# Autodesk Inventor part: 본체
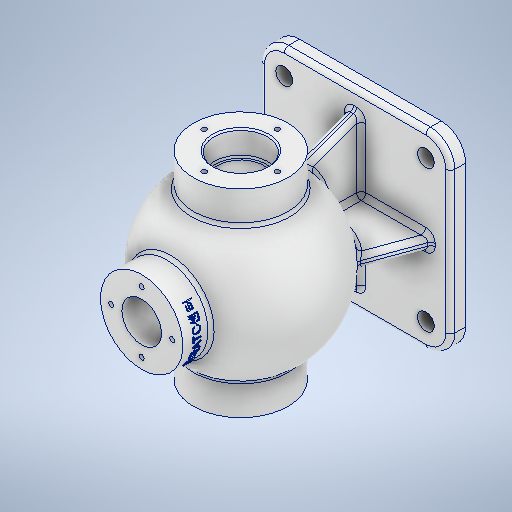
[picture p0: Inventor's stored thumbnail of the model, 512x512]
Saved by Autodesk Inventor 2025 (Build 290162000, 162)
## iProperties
Created: 2025-08
Part Number: 본체
Material: 알루미늄 6061
Document SubType Name: Modeling
Designer: infra028
Density: 2.7 g/cm^3
Appearance: 알루미늄 - 평지
Mass: 1526.56 g
Surface Area: 1173.66 cm^2
Volume: 565.392 cm^3
Author: infra028
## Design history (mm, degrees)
sketch "스케치1"
  geometry: L1 (-62.5, 62.5)-(62.5, 62.5); L2 (62.5, 62.5)-(62.5, -62.5); L3 (62.5, -62.5)-(-62.5, -62.5); L4 (-62.5, -62.5)-(-62.5, 62.5); L5 (-62.5, 62.5)-(62.5, -62.5); L6 (62.5, 62.5)-(-62.5, -62.5); 1 further point
  constraints: 12 end point, 2 midpoint, 2 parallel, 1 horizontal, 1 perpendicular
  dimensions: "d0" = 125 distance of L2.end L3.end; "d1" = 125 distance of L1.end L2.end
extrude "돌출1" new body sketch "스케치1" distance "d2" = 10; taper "d3" = 0 deg
sketch "스케치2"
  geometry: L1 (-46.5, 46.5)-(46.5, 46.5); L2 (46.5, 46.5)-(46.5, -46.5); L3 (46.5, -46.5)-(-46.5, -46.5); L4 (-46.5, -46.5)-(-46.5, 46.5); L5 (62.5, -62.5)-(62.5, 62.5) reference; L6 (-62.5, 62.5)-(-62.5, -62.5) reference; L7 (62.5, 62.5)-(-62.5, 62.5) reference; L8 (-62.5, -62.5)-(62.5, -62.5) reference; 5 further points
  constraints: 8 end point, 4 coincident, 2 parallel, 1 horizontal, 1 perpendicular
  dimensions: "d4" = 93 distance of L2.end L3.end; "d5" = 93 distance of L1.end L2.end; "d6" = 16 distance between parallel lines of L5 L2 (= d7); "d7" = 16 distance between parallel lines of L4 L6 (derived); "d8" = 16 distance between parallel lines of L1 L7 (= d9); "d9" = 16 distance between parallel lines of L8 L3 (derived)
hole "구멍1" sketch "스케치2" at (46.5, 46.5), (-46.5, -46.5), (46.5, -46.5), (-46.5, 46.5) diameter "d10" = 11; stored, may be unused: countersink angle "d14" = 90 deg, drill point angle "d16" = 0 deg; dims "d11" = 8, "d12" = 4, "d13" = 2, "d15" = 11.8
sketch "스케치4"
  geometry: L1 (54, 85)-(-54, 85); L2 (62.5, 0)-(-62.5, 0) reference; L3 (62.5, 0)-(62.5, 10) reference; A1 r 54 centre (0, 85) between (54, 85) and (-54, 85); 3 further points
  constraints: 2 end point, 2 midpoint, 2 point on circle, 1 centre point, 1 horizontal
  dimensions: "d18" = 108 diameter of A1; "d20" = 85 distance from line of L2 point (0, 85); "d21" = 62.5 horizontal distance of A1.centre point (62.5, 5); "d22" = 8.5 distance from line of L1.start L3
revolve "회전1" sketch "스케치4" stored, may be unused: angle "d19" = 360 deg
sketch "스케치5"
  geometry: L1 (-62.5, 10)-(62.5, 10) reference; L2 (-34.447, 54.104)-(-50.5, 10); L3 (43.084, 10)-(-50.5, 10); L4 (62.5, 0)-(62.5, 10) reference; L5 (-62.5, 0)-(-62.5, 10) reference; L6 (50.5, 10)-(34.447, 54.104); L7 (34.447, 54.104)-(-34.447, 54.104); 1 further point
  constraints: 8 end point, 3 point on line, 1 horizontal
  dimensions: "d24" = 20 deg angle of L2 L5; "d25" = 20 deg angle of L4 L6; "d26" = 12 distance from line of L6.start L4; "d27" = 12 distance of L1.start L2.end; "d28" = 44.10432 distance between parallel lines of L1 L7
extrude "돌출2" join sketch "스케치5" stored distance "d29" = 8; taper "d30" = 0 deg
sketch "스케치6"
  geometry: L1 (50.5, 10)-(33.738, 56.054); L2 (62.5, 0)-(62.5, 10) reference; L3 (-62.5, 10)-(62.5, 10) reference; L4 (-50.5, 10)-(-33.738, 56.054); L5 (-62.5, 0)-(-62.5, 10) reference; L6 (33.738, 56.054)-(-33.738, 56.054); 1 further point
  constraints: 6 end point, 2 point on line, 1 horizontal
  dimensions: "d31" = 20 deg angle of L2 L1; "d32" = 12 distance of L2.end L1.start; "d33" = 20 deg angle of L5 L4; "d34" = 12 distance of L3.start L4.start; "d35" = 46.0543 distance between parallel lines of L3 L6
extrude "돌출3" join sketch "스케치6" stored distance "d36" = 8; taper "d37" = 0 deg
sketch "스케치7"
  geometry: L1 (0, 85)-(-65, 85); L2 (-65, 85)-(-65, 116); L3 (-65, 116)-(-37.385, 116); L4 (-37.385, 116)-(-37.385, 85); 1 further point
  constraints: 8 end point, 2 horizontal, 2 perpendicular, 1 point on line
  dimensions: "d38" = 65 distance of L1.start L1.end; "d39" = 31 distance of L1.end L2.end; "d40" = 27.61518 distance between parallel lines of L4 L2; "d41" = 85 distance from line of point (0, 0) L1; "d42" = 37.38482 distance from line of point (0, 0) L4
revolve "회전2" sketch "스케치7" stored, may be unused: angle "d43" = 360 deg
sketch "스케치8"
  geometry: L1 (0, 85)-(0, 150); L2 (27, 150)-(-27, 150); L3 (27, 150)-(27, 124.409); L4 (27, 124.409)-(-27, 124.409); L5 (-27, 124.409)-(-27, 150); L6 (27, 137.204)-(-27, 137.204); A1 r 54 centre (0, 85) between (37.385, 46.034) and (-37.385, 46.034) reference; 5 further points
  constraints: 12 end point, 3 midpoint, 2 perpendicular, 2 vertical, 1 coincident, 1 horizontal
  dimensions: "d44" = 65 distance of L1.end L1.start; "d45" = 54 distance of L2.start L2.end; "d46" = 25.59142 distance between parallel lines of L4 L2
revolve "회전3" sketch "스케치8" stored, may be unused: angle "d47" = 360 deg
sketch "스케치9"
  geometry: L1 (65, 116)-(65, 54) reference; L2 (-65, 116)-(-65, 54) reference; L3 (65, 85)-(-65, 85); L4 (65, 102.5)-(49, 102.5); L5 (49, 102.5)-(49, 100); L6 (49, 100)-(41.364, 100); L7 (-65, 102.5)-(-49, 102.5); L8 (-49, 102.5)-(-49, 100); L9 (-49, 100)-(-41.364, 100); A1 r 54 centre (0, 85) between (37.385, 46.034) and (-37.385, 46.034) reference; A2 r 44 centre (0, 85) between (41.364, 100) and (-41.364, 100); 1 further point
  constraints: 14 end point, 5 perpendicular, 2 midpoint, 2 point on circle, 2 point on line, 1 centre point, 1 coincident, 1 horizontal
  dimensions: "d48" = 88 diameter of A2; "d49" = 17.5 distance between parallel lines of L3 L4; "d50" = 15 distance between parallel lines of L3 L6; "d51" = 16 distance between parallel lines of L1 L5; "d52" = 17.5 distance between parallel lines of L3 L7; "d53" = 15 distance between parallel lines of L3 L9; "d54" = 16 distance between parallel lines of L2 L8
revolve "회전4" sketch "스케치9" stored, may be unused: angle "d55" = 360 deg
sketch "스케치10"
  geometry: L1 (-41.364, 100)-(-41.364, 70) reference; L2 (41.364, 100)-(41.364, 70) reference; L3 (27, 150)-(-27, 150) reference; L4 (13, 150)-(13, 127.036); L5 (0, 150)-(0, 129); A1 r 44 centre (0, 85) between (41.364, 100) and (41.364, 70) reference; 1 further point
  constraints: 4 end point, 2 point on circle, 1 midpoint, 1 parallel, 1 perpendicular, 1 point on line
  dimensions: "d56" = 13 distance between parallel lines of L5 L4
revolve "회전5" sketch "스케치10" stored, may be unused: angle "d57" = 360 deg
sketch "스케치13"
  geometry: L1 (0, 0)-(0, -24); C1 r 17.5 at (0, 0) reference; 5 further points
  constraints: 2 end point, 1 coincident, 1 vertical, 5 other
  dimensions: "d58" = 24 distance of L1.start L1.end; "d61" = 360 deg dimension on L1.start point (0, -24) (derived)
hole "구멍2" sketch "스케치13" at (0, -24), (24, 0), (0, 24), (-24, 0) diameter "d63" = 3.242; stored, may be unused: countersink angle "d67" = 90 deg, drill point angle "d69" = 118 deg; dims "d64" = 12, "d65" = 4, "d66" = 2, "d68" = 15
sketch "스케치14"
  geometry: L1 (0, 0)-(0, 20); 4 further points
  constraints: 2 end point, 1 coincident, 1 vertical, 5 other
  dimensions: "d70" = 20 distance of L1.start L1.end; "d73" = 360 deg dimension on L1.start point (0, 20) (derived)
hole "구멍3" sketch "스케치14" at (0, 20), (-20, 0), (0, -20), (20, 0) diameter "d75" = 3.242; stored, may be unused: countersink angle "d79" = 90 deg, drill point angle "d81" = 118 deg; dims "d76" = 9, "d77" = 4, "d78" = 2, "d80" = 11
fillet "모깎기1" dims "d82" = 16
fillet "모깎기2" dims "d83" = 3
fillet "모깎기3" dims "d84" = 3
fillet "모깎기4" dims "d85" = 3
fillet "모깎기5" dims "d86" = 3
fillet "모깎기6" dims "d87" = 3
chamfer "모따기1" distance "d88" = 1; stored, may be unused: second distance "d89" = 2, angle "d90" = 45 deg
chamfer "모따기2" distance "d91" = 1; stored, may be unused: second distance "d92" = 2, angle "d93" = 45 deg
chamfer "모따기3" distance "d94" = 1; stored, may be unused: second distance "d95" = 2, angle "d96" = 45 deg
chamfer "모따기4" distance "d97" = 1; stored, may be unused: second distance "d98" = 2, angle "d99" = 45 deg
node "작업 평면3"
sketch "스케치17"
  geometry: L1 (-15.721, 8.433)-(15.721, 8.433); L2 (15.721, 8.433)-(15.721, -0.842); L3 (15.721, -0.842)-(-15.721, -0.842); L4 (-15.721, -0.842)-(-15.721, 8.433); L5 (27, 12.796)-(-27, 12.796) reference; L6 (-46.5, -137.204)-(46.5, -137.204) reference; 5 further points
  constraints: 4 midpoint, 1 vertical alignment, 2 other
  dimensions: "d102" = 9 distance from line of point (-15.721, 3.796) L5
feature "엠보싱1" sketch "스케치17" dims "d0" = 125, "d1" = 125, "d14" = 90 deg, "d103" = 0.5, "d104" = 0
feature "Ї耀Љ耀Ћ耀Ѝ耀Џ耀Б耀Г耀Е耀" dims "d0" = 125, "d1" = 125, "d2" = 10, "d3" = 0, "d4" = 93, "d5" = 93, "d6" = 16 (= d7), "d7" = 16 (derived), "d8" = 16 (= d9), "d9" = 16 (derived), "d10" = 11, "d11" = 8, "d12" = 4, "d13" = 2, "d14" = 90 deg, "d15" = 11.8, "d16" = 0, "d18" = 108, "d19" = 360 deg, "d20" = 85, "d21" = 62.5, "d22" = 8.5, "d24" = 20 deg, "d25" = 20 deg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
node "솔리드1"
mirror "미러1"
mirror "미러3"
node "작업 평면1"
node "투영된 루프1"
node "스케치 - 원형 패턴1" dims "d61" = 360 deg (derived)
node "스케치 - 원형 패턴2" dims "d73" = 360 deg (derived)
feature "A9D066F2-1C7D-4E18-AEED-F7BC21143FA4" dims "d10" = 11, "d11" = 8, "d12" = 4, "d13" = 2, "d14" = 90 deg, "d15" = 11.8, "d16" = 0
